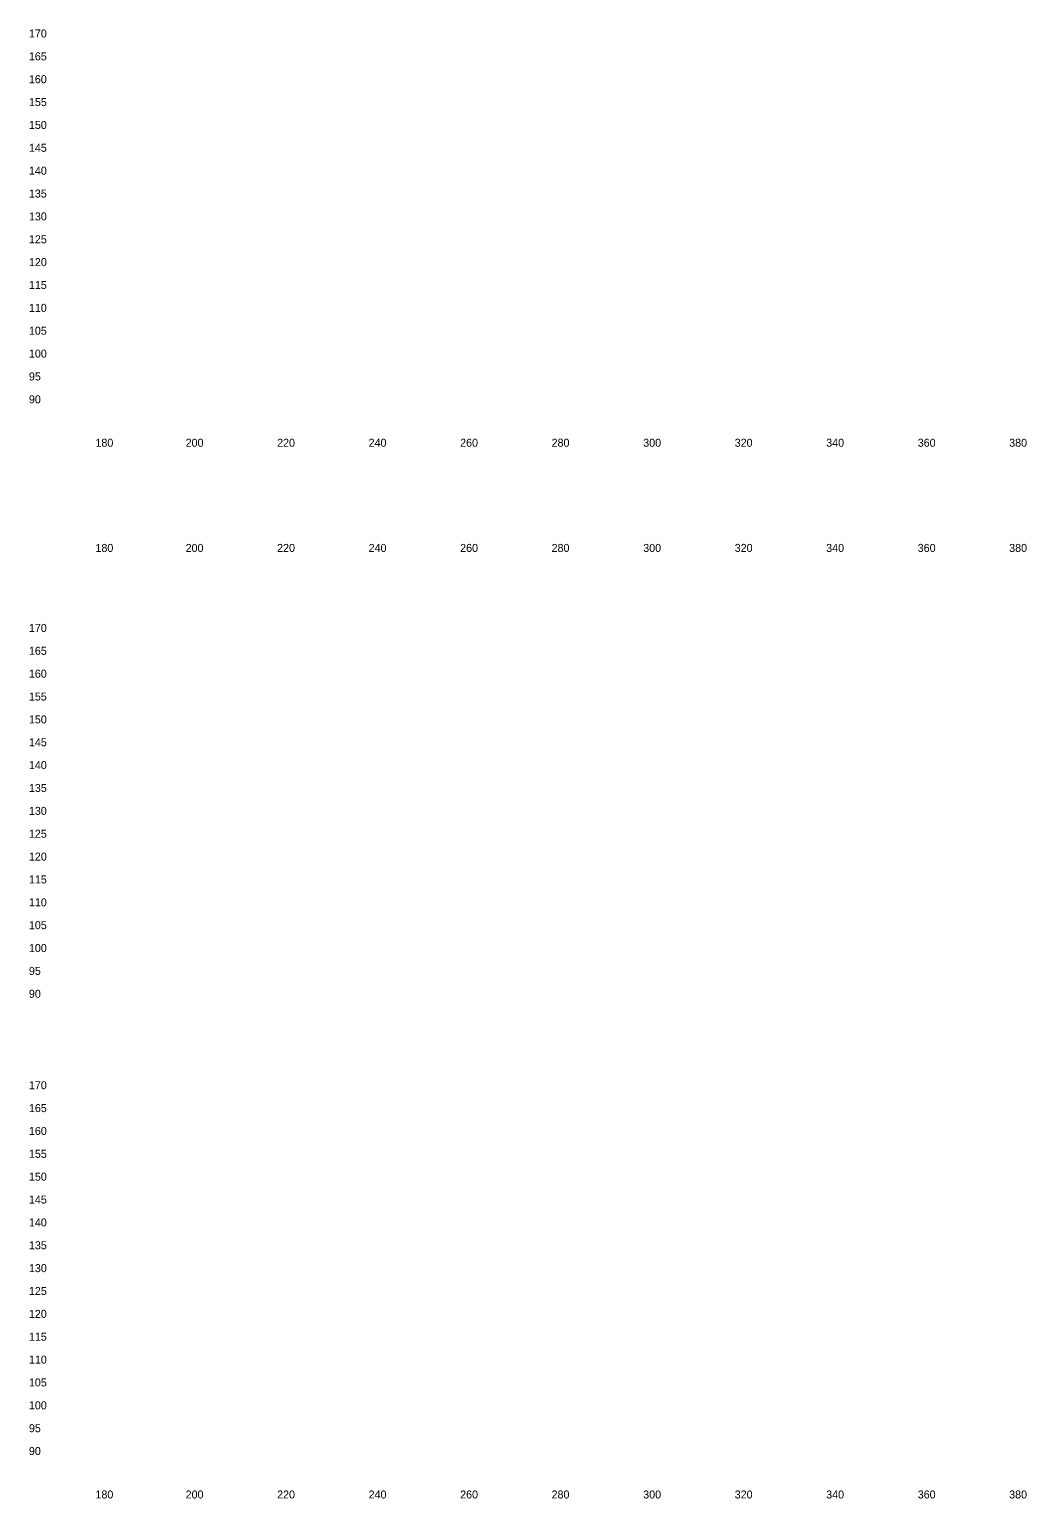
# Model space of a CAD drawing. Extents: x 21059 to 22955, y 6470 to 17494.
# Drawn here: x 21806.2 to 22024.2, y 11995.3 to 12316.6 of the extents above; entities that cross this region are included whole.
import ezdxf

# ---------------------------------------------------------------- set-up
doc = ezdxf.new("R2010")
doc.units = 0
doc.layers.add('Draft_XS_Grid', color=7, linetype='Continuous')
doc.layers.add('Draft_XS_Text', color=7, linetype='Continuous')

msp = doc.modelspace()

# ---------------------------------------------------------------- texts
at = {"layer": 'Draft_XS_Grid'}
for s, p in [('  170  ', (21804.84, 12314.84)), ('  165  ', (21804.84, 12309.84)), ('  160  ', (21804.84, 12304.84)), ('  155  ', (21804.84, 12299.84)), ('  150  ', (21804.84, 12294.84)), ('  145  ', (21804.84, 12289.84)), ('  140  ', (21804.84, 12284.84)), ('  135  ', (21804.84, 12279.84)), ('  130  ', (21804.84, 12274.84)), ('  125  ', (21804.84, 12269.84)), ('  120  ', (21804.84, 12264.84)), ('  115  ', (21804.84, 12259.84)), ('  110  ', (21804.84, 12254.84)), ('  105  ', (21804.84, 12249.84)), ('  100  ', (21804.84, 12244.84)), ('  95  ', (21804.84, 12239.84)), ('  90  ', (21804.84, 12234.84)), ('  170  ', (21804.84, 12184.84)), ('  165  ', (21804.84, 12179.84)), ('  160  ', (21804.84, 12174.84)), ('  155  ', (21804.84, 12169.84)), ('  150  ', (21804.84, 12164.84)), ('  145  ', (21804.84, 12159.84)), ('  140  ', (21804.84, 12154.84)), ('  135  ', (21804.84, 12149.84)), ('  130  ', (21804.84, 12144.84)), ('  125  ', (21804.84, 12139.84)), ('  120  ', (21804.84, 12134.84)), ('  115  ', (21804.84, 12129.84)), ('  110  ', (21804.84, 12124.84)), ('  105  ', (21804.84, 12119.84)), ('  100  ', (21804.84, 12114.84)), ('  95  ', (21804.84, 12109.84)), ('  90  ', (21804.84, 12104.84)), ('  170  ', (21804.84, 12084.84)), ('  165  ', (21804.84, 12079.84)), ('  160  ', (21804.84, 12074.84)), ('  155  ', (21804.84, 12069.84)), ('  150  ', (21804.84, 12064.84)), ('  145  ', (21804.84, 12059.84)), ('  140  ', (21804.84, 12054.84)), ('  135  ', (21804.84, 12049.84)), ('  130  ', (21804.84, 12044.84)), ('  125  ', (21804.84, 12039.84)), ('  120  ', (21804.84, 12034.84)), ('  115  ', (21804.84, 12029.84)), ('  110  ', (21804.84, 12024.84)), ('  105  ', (21804.84, 12019.84)), ('  100  ', (21804.84, 12014.84)), ('  95  ', (21804.84, 12009.84)), ('  90  ', (21804.84, 12004.84))]:
    msp.add_text(s, height=1.75, dxfattribs=at).set_placement(p)
at = {"layer": 'Draft_XS_Text'}
for s, p in [('  180  ', (21819.39, 12225.34)), ('  200  ', (21839.1, 12225.34)), ('  220  ', (21859.1, 12225.34)), ('  240  ', (21879.1, 12225.34)), ('  260  ', (21899.11, 12225.34)), ('  280  ', (21919.1, 12225.34)), ('  300  ', (21939.13, 12225.34)), ('  320  ', (21959.13, 12225.34)), ('  340  ', (21979.13, 12225.34)), ('  360  ', (21999.14, 12225.34)), ('  380  ', (22019.13, 12225.34)), ('  180  ', (21819.39, 12202.34)), ('  200  ', (21839.1, 12202.34)), ('  220  ', (21859.1, 12202.34)), ('  240  ', (21879.1, 12202.34)), ('  260  ', (21899.11, 12202.34)), ('  280  ', (21919.1, 12202.34)), ('  300  ', (21939.13, 12202.34)), ('  320  ', (21959.13, 12202.34)), ('  340  ', (21979.13, 12202.34)), ('  360  ', (21999.14, 12202.34)), ('  380  ', (22019.13, 12202.34)), ('  180  ', (21819.39, 11995.34)), ('  200  ', (21839.1, 11995.34)), ('  220  ', (21859.1, 11995.34)), ('  240  ', (21879.1, 11995.34)), ('  260  ', (21899.11, 11995.34)), ('  280  ', (21919.1, 11995.34)), ('  300  ', (21939.13, 11995.34)), ('  320  ', (21959.13, 11995.34)), ('  340  ', (21979.13, 11995.34)), ('  360  ', (21999.14, 11995.34)), ('  380  ', (22019.13, 11995.34))]:
    msp.add_text(s, height=1.75, dxfattribs=at).set_placement(p)

doc.saveas('drawing.dxf')
